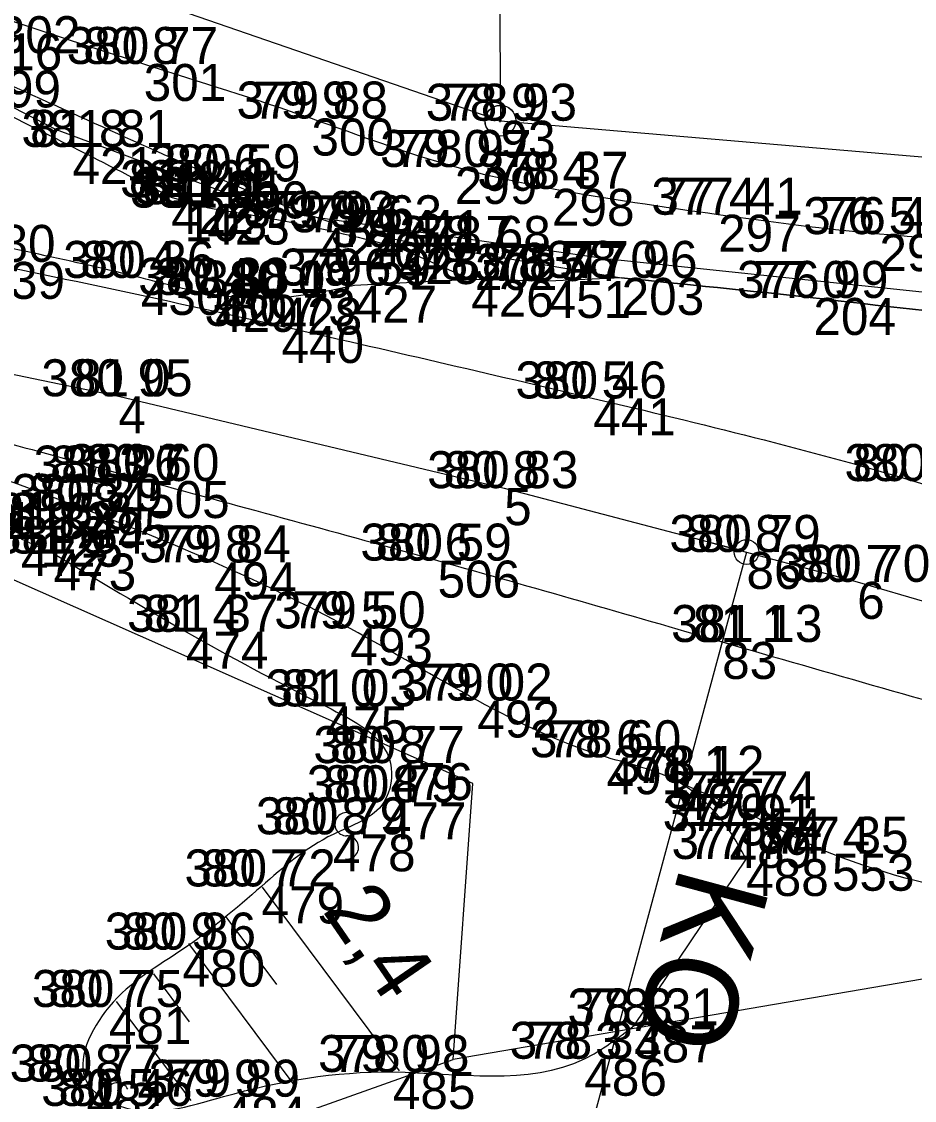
# Model space of a CAD drawing. Extents: x -514509 to -512782, y -1144610 to -1143439.
# Drawn here: x -513064.89 to -513035.93, y -1143617.66 to -1143582.66 of the extents above; entities that cross this region are included whole.
import ezdxf

# ---------------------------------------------------------------- set-up
doc = ezdxf.new("R2010")
doc.units = 0
for name, color, linetype in [('Vrstva 1', 7, 'Continuous'), ('Vrstva 10', 7, 'Continuous'), ('Vrstva 11', 7, 'Continuous'), ('Vrstva 12', 7, 'Continuous'), ('Vrstva 18', 7, 'Continuous'), ('Vrstva 38', 7, 'Continuous'), ('Vrstva 39', 7, 'Continuous'), ('Vrstva 48', 7, 'Continuous'), ('Vrstva 57', 7, 'Continuous'), ('Vrstva 58', 7, 'Continuous'), ('Vrstva 59', 7, 'Continuous'), ('Vrstva 6', 7, 'Continuous'), ('Vrstva 60', 7, 'Continuous'), ('Vrstva 8', 7, 'Continuous')]:
    doc.layers.add(name, color=color, linetype=linetype)

msp = doc.modelspace()

# ---------------------------------------------------------------- linework, layer by layer
at = {"layer": 'Vrstva 1'}
msp.add_lwpolyline([(-513220.491, -1143575.228), (-513193.623, -1143570.982), (-513176.915, -1143569.129), (-513155.694, -1143568.05), (-513138.074, -1143568.989), (-513122.982, -1143570.739), (-513098.68, -1143574.346), (-513082.799, -1143577.731), (-513077.892, -1143579.384), (-513072.257, -1143581.789), (-513063.773, -1143586.163), (-513056.631, -1143588.823), (-513045.948, -1143590.353), (-513035.79, -1143591.42), (-513027.577, -1143592.226), (-513018.616, -1143594.003), (-513003.093, -1143598.799), (-512994.741, -1143602.979), (-512987.23, -1143608.317)], dxfattribs=at)
at = {"layer": 'Vrstva 10'}
for p, q in [((-513049.412, -1143585.881), (-513049.312, -1143585.881)), ((-513049.412, -1143585.881), (-513049.312, -1143585.881)), ((-513049.412, -1143585.881), (-513049.312, -1143585.881)), ((-513049.412, -1143585.881), (-513049.312, -1143585.881)), ((-513049.371, -1143585.929), (-513049.349, -1143585.831)), ((-513049.371, -1143585.929), (-513049.349, -1143585.831)), ((-513049.371, -1143585.929), (-513049.349, -1143585.831))]:
    msp.add_line(p, q, dxfattribs=at)
for points in [[(-513082.58, -1143574.42), (-513049.36, -1143585.88), (-513032.15, -1143587.352), (-513013.645, -1143592.585), (-512996.08, -1143600.301), (-512976.442, -1143595.705), (-512976.456, -1143612.872), (-512962.931, -1143616.56), (-512954.194, -1143606.538), (-512930.452, -1143592.642), (-512928.362, -1143585.895), (-512925.699, -1143603.347)], [(-513082.58, -1143574.42), (-513049.36, -1143585.88), (-513032.15, -1143587.352), (-513013.645, -1143592.585), (-512996.08, -1143600.301), (-512976.442, -1143595.705), (-512976.456, -1143612.872), (-512962.931, -1143616.56), (-512954.194, -1143606.538), (-512930.452, -1143592.642), (-512928.362, -1143585.895), (-512925.699, -1143603.347)], [(-513060.043, -1143588.357), (-513058.868, -1143588.697)], [(-513052.691, -1143589.985), (-513050.308, -1143591.036), (-513054.09, -1143591.229)], [(-513050.191, -1143590.168), (-513045.435, -1143590.979)], [(-513050.191, -1143590.168), (-513045.435, -1143590.979)], [(-513045.435, -1143590.979), (-513047.8, -1143591.081), (-513050.308, -1143591.036)], [(-513064.908, -1143599.447), (-513063.854, -1143599.92)], [(-512782.341, -1143656.666), (-512796.89, -1143661.893), (-512815.309, -1143658.506), (-512846.358, -1143662.813), (-512847.692, -1143673.887), (-512850.552, -1143675.414), (-512874.542, -1143673.507), (-512907.663, -1143668.822), (-512937.442, -1143663.927), (-512942.033, -1143670.511), (-512944.784, -1143662.787), (-512958.978, -1143654.892), (-512977.284, -1143642.016), (-512997.25, -1143628.575), (-513034.474, -1143613.524), (-513050.89, -1143616.331), (-513050.251, -1143607.386), (-513065.331, -1143600.696), (-513084.436, -1143602.206), (-513086.215, -1143618.123), (-513093.877, -1143618.167), (-513107.772, -1143623.787)], [(-512782.341, -1143656.666), (-512796.89, -1143661.893), (-512815.309, -1143658.506), (-512846.358, -1143662.813), (-512847.692, -1143673.887), (-512850.552, -1143675.414), (-512874.542, -1143673.507), (-512907.663, -1143668.822), (-512937.442, -1143663.927), (-512942.033, -1143670.511), (-512944.784, -1143662.787), (-512958.978, -1143654.892), (-512977.284, -1143642.016), (-512997.25, -1143628.575), (-513034.474, -1143613.524), (-513050.89, -1143616.331), (-513050.251, -1143607.386), (-513065.331, -1143600.696), (-513084.436, -1143602.206), (-513086.215, -1143618.123), (-513093.877, -1143618.167), (-513107.772, -1143623.787)], [(-513041.608, -1143608.193), (-513043.544, -1143607.361)], [(-513045.021, -1143615.229), (-513041.387, -1143609.834)], [(-513057.086, -1143610.749), (-513052.65, -1143616.702)], [(-513058.27, -1143611.707), (-513056.621, -1143613.897)], [(-513059.477, -1143612.573), (-513056.026, -1143617.204)], [(-513060.615, -1143613.559), (-513059.458, -1143615.112)], [(-513061.818, -1143614.456), (-513059.403, -1143617.66)]]:
    msp.add_lwpolyline(points, dxfattribs=at)
for centre in [(-513049.362, -1143585.881), (-513049.362, -1143585.881), (-513049.362, -1143585.881), (-513049.362, -1143585.881), (-513049.36, -1143585.88), (-513049.36, -1143585.88), (-513049.36, -1143585.88)]:
    msp.add_circle(centre, 0.499, dxfattribs=at)
for points in [[(-512953.995, -1143613.026), (-512957.258, -1143613.803), (-512961.396, -1143614.272), (-512966.482, -1143614.31), (-512970.759, -1143614.088), (-512973.268, -1143613.625), (-512976.312, -1143612.767), (-512979.387, -1143610.931), (-512983.271, -1143608.165), (-512988.084, -1143604.174), (-512993.595, -1143600.71), (-512999.183, -1143597.931), (-513003.859, -1143595.565), (-513008.344, -1143594.112), (-513012.116, -1143593.309), (-513017.24, -1143592.33), (-513022.405, -1143591.458), (-513027.962, -1143590.755), (-513032.282, -1143589.984), (-513037.071, -1143589.561), (-513042.298, -1143588.932), (-513047.694, -1143588.089), (-513050.837, -1143587.38), (-513055.493, -1143585.813), (-513060.929, -1143584.042), (-513065.663, -1143582.489), (-513071.062, -1143580.47), (-513076.142, -1143578.183), (-513080.606, -1143576.177), (-513085.081, -1143574.916), (-513090.677, -1143573.538)], [(-512953.995, -1143613.026), (-512957.258, -1143613.803), (-512961.396, -1143614.272), (-512966.482, -1143614.31), (-512970.759, -1143614.088), (-512973.268, -1143613.625), (-512976.312, -1143612.767), (-512979.387, -1143610.931), (-512983.271, -1143608.165), (-512988.084, -1143604.174), (-512993.595, -1143600.71), (-512999.183, -1143597.931), (-513003.859, -1143595.565), (-513008.344, -1143594.112), (-513012.116, -1143593.309), (-513017.24, -1143592.33), (-513022.405, -1143591.458), (-513027.962, -1143590.755), (-513032.282, -1143589.984), (-513037.071, -1143589.561), (-513042.298, -1143588.932), (-513047.694, -1143588.089), (-513050.837, -1143587.38), (-513055.493, -1143585.813), (-513060.929, -1143584.042), (-513065.663, -1143582.489), (-513071.062, -1143580.47), (-513076.142, -1143578.183), (-513080.606, -1143576.177), (-513085.081, -1143574.916), (-513090.677, -1143573.538)], [(-513075.063, -1143581.2), (-513072.454, -1143581.842), (-513066.293, -1143584.252), (-513058.25, -1143587.854), (-513053.706, -1143589.505), (-513050.191, -1143590.168)], [(-513075.063, -1143581.2), (-513072.454, -1143581.842), (-513066.293, -1143584.252), (-513058.25, -1143587.854), (-513053.706, -1143589.505), (-513050.191, -1143590.168)], [(-513075.344, -1143581.563), (-513068.994, -1143583.976), (-513063.238, -1143586.73), (-513060.043, -1143588.357)], [(-513054.09, -1143591.229), (-513056.524, -1143591.625), (-513058.608, -1143591.528), (-513061.016, -1143590.979), (-513067.66, -1143589.521), (-513078.163, -1143587.246), (-513090.745, -1143584.896)], [(-513094.522, -1143585.424), (-513085.972, -1143586.813), (-513077.096, -1143588.391), (-513066.158, -1143590.465), (-513056.46, -1143592.544), (-513046.346, -1143594.887), (-513035.955, -1143597.575), (-513025.704, -1143600.949), (-513014.943, -1143604.21), (-513004.729, -1143607.491)], [(-513058.868, -1143588.697), (-513055.265, -1143589.361), (-513052.691, -1143589.985)], [(-513045.435, -1143590.979), (-513039.213, -1143591.629), (-513032.779, -1143592.299), (-513026.133, -1143592.81), (-513019.57, -1143594.143), (-513014.993, -1143595.23), (-513009.333, -1143597.099), (-513004.427, -1143598.943), (-513000.195, -1143600.648), (-512995.465, -1143603.755), (-512990.482, -1143606.95), (-512986.481, -1143609.695), (-512982.688, -1143612.309), (-512979.1, -1143614.259), (-512976.081, -1143615.456), (-512973.855, -1143616.04), (-512971.299, -1143616.182), (-512967.877, -1143616.452), (-512963.669, -1143616.372), (-512959.668, -1143616.236), (-512956.333, -1143615.735)], [(-513045.435, -1143590.979), (-513039.213, -1143591.629), (-513032.779, -1143592.299), (-513026.133, -1143592.81), (-513019.57, -1143594.143), (-513014.993, -1143595.23), (-513009.333, -1143597.099), (-513004.427, -1143598.943), (-513000.195, -1143600.648), (-512995.465, -1143603.755), (-512990.482, -1143606.95), (-512986.481, -1143609.695), (-512982.688, -1143612.309), (-512979.1, -1143614.259), (-512976.081, -1143615.456), (-512973.855, -1143616.04), (-512971.299, -1143616.182), (-512967.877, -1143616.452), (-512963.669, -1143616.372), (-512959.668, -1143616.236), (-512956.333, -1143615.735)], [(-512979.1, -1143614.259), (-512982.688, -1143612.309), (-512986.481, -1143609.695), (-512990.482, -1143606.95), (-512995.465, -1143603.755), (-513000.195, -1143600.648), (-513004.427, -1143598.943), (-513009.333, -1143597.099), (-513014.993, -1143595.23), (-513019.57, -1143594.143), (-513026.133, -1143592.81), (-513032.779, -1143592.299), (-513039.213, -1143591.629), (-513045.435, -1143590.979)], [(-513091.48, -1143591.211), (-513084.48, -1143592.318), (-513076.865, -1143593.708), (-513068.286, -1143595.582), (-513060.823, -1143597.567), (-513051.402, -1143600.148), (-513042.167, -1143602.79), (-513031.788, -1143605.729), (-513027.378, -1143606.917)], [(-513041.387, -1143609.834), (-513041.931, -1143608.916), (-513043.544, -1143607.361), (-513045.917, -1143606.531), (-513050.108, -1143604.688), (-513054.233, -1143602.354), (-513058.64, -1143600.206), (-513062.712, -1143598.536), (-513069.216, -1143596.302), (-513075.014, -1143594.932), (-513083.059, -1143593.63), (-513093.377, -1143592.318)], [(-513063.854, -1143599.92), (-513059.557, -1143602.457), (-513055.027, -1143604.877), (-513052.926, -1143606.719), (-513053.141, -1143607.989), (-513054.788, -1143609.032), (-513057.112, -1143610.72), (-513059.667, -1143612.765), (-513062.056, -1143614.633), (-513062.783, -1143617.052), (-513061.726, -1143617.841), (-513058.344, -1143617.537), (-513052.854, -1143616.739), (-513046.637, -1143616.314), (-513045.021, -1143615.229)], [(-512993.539, -1143625.829), (-513001.654, -1143622.116), (-513007.851, -1143619.347), (-513015.061, -1143617.108), (-513021.554, -1143615.482), (-513027.253, -1143613.027), (-513033.075, -1143611.223), (-513038.613, -1143609.661), (-513041.608, -1143608.193)]]:
    msp.add_spline(points, degree=3, dxfattribs=at)
at = {"layer": 'Vrstva 12'}
for p, q in [((-513062.479, -1143597.131), (-513062.696, -1143598.108)), ((-513063.076, -1143597.511), (-513062.099, -1143597.728)), ((-513042.036, -1143602.307), (-513042.297, -1143603.272)), ((-513042.649, -1143602.659), (-513041.684, -1143602.92))]:
    msp.add_line(p, q, dxfattribs=at)
at = {"layer": 'Vrstva 18'}
for centre, radius, start, end in [((-513054.353, -1143608.702), 0.376, 84.3625, 270.6736), ((-513054.34, -1143609.455), 0.377, 263.6864, 91.3496), ((-513061.786, -1143617.464), 0.376, 25.7026, 212.0138)]:
    msp.add_arc(centre, radius, start, end, dxfattribs=at)
at = {"layer": 'Vrstva 38'}
msp.add_circle((-513041.38, -1143599.872), 0.4, dxfattribs=at)
at = {"layer": 'Vrstva 39'}
msp.add_lwpolyline([(-513041.38, -1143599.872), (-513042.167, -1143602.79), (-513051.797, -1143638.491)], dxfattribs=at)
at = {"layer": 'Vrstva 48'}
msp.add_line((-513049.412, -1143585.881), (-513049.312, -1143585.881), dxfattribs=at)
msp.add_circle((-513049.362, -1143585.881), 0.499, dxfattribs=at)
at = {"layer": 'Vrstva 6'}
for points in [[(-513098.478, -1143588.28), (-513086.339, -1143590.12), (-513074.133, -1143592.245), (-513061.751, -1143594.815), (-513049.24, -1143597.798), (-513041.788, -1143599.762)], [(-513042.471, -1143599.582), (-513037.794, -1143600.839), (-513025.951, -1143604.295), (-513021.487, -1143605.723), (-513009.806, -1143609.501), (-513001.948, -1143612.085)]]:
    msp.add_lwpolyline(points, dxfattribs=at)
at = {"layer": 'Vrstva 60'}
for p, q in [((-513060.93, -1143584.04), (-513060.93, -1143584.04)), ((-513055.49, -1143585.81), (-513055.49, -1143585.81)), ((-513049.36, -1143585.88), (-513049.36, -1143585.88)), ((-513063.24, -1143586.73), (-513063.24, -1143586.73)), ((-513050.84, -1143587.38), (-513050.84, -1143587.38)), ((-513058.25, -1143587.85), (-513058.25, -1143587.85)), ((-513047.69, -1143588.09), (-513047.69, -1143588.09)), ((-513060.04, -1143588.36), (-513060.04, -1143588.36)), ((-513059.6, -1143588.59), (-513059.6, -1143588.59)), ((-513058.87, -1143588.7), (-513058.87, -1143588.7)), ((-513042.3, -1143588.93), (-513042.3, -1143588.93)), ((-513055.26, -1143589.36), (-513055.26, -1143589.36)), ((-513053.71, -1143589.5), (-513053.71, -1143589.5)), ((-513037.07, -1143589.56), (-513037.07, -1143589.56)), ((-513052.69, -1143589.98), (-513052.69, -1143589.98)), ((-513050.19, -1143590.17), (-513050.19, -1143590.17)), ((-513061.02, -1143590.98), (-513061.02, -1143590.98)), ((-513045.43, -1143590.98), (-513045.43, -1143590.98)), ((-513054.09, -1143591.23), (-513054.09, -1143591.23)), ((-513050.31, -1143591.04), (-513050.31, -1143591.04)), ((-513047.8, -1143591.08), (-513047.8, -1143591.08)), ((-513058.61, -1143591.53), (-513058.61, -1143591.53)), ((-513056.52, -1143591.62), (-513056.52, -1143591.62)), ((-513039.21, -1143591.63), (-513039.21, -1143591.63)), ((-513056.46, -1143592.54), (-513056.46, -1143592.54)), ((-513061.75, -1143594.82), (-513061.75, -1143594.82)), ((-513046.35, -1143594.89), (-513046.35, -1143594.89)), ((-513062.59, -1143597.62), (-513062.59, -1143597.62)), ((-513060.82, -1143597.57), (-513060.82, -1143597.57)), ((-513035.96, -1143597.57), (-513035.96, -1143597.57)), ((-513049.24, -1143597.8), (-513049.24, -1143597.8)), ((-513062.71, -1143598.54), (-513062.71, -1143598.54)), ((-513064.28, -1143599.15), (-513064.28, -1143599.15)), ((-513063.85, -1143599.92), (-513063.85, -1143599.92)), ((-513041.38, -1143599.87), (-513041.38, -1143599.87)), ((-513058.64, -1143600.21), (-513058.64, -1143600.21)), ((-513051.4, -1143600.15), (-513051.4, -1143600.15)), ((-513037.79, -1143600.84), (-513037.79, -1143600.84)), ((-513059.56, -1143602.46), (-513059.56, -1143602.46)), ((-513054.23, -1143602.35), (-513054.23, -1143602.35)), ((-513042.17, -1143602.79), (-513042.17, -1143602.79)), ((-513055.03, -1143604.88), (-513055.03, -1143604.88)), ((-513050.11, -1143604.69), (-513050.11, -1143604.69)), ((-513052.93, -1143606.72), (-513052.93, -1143606.72)), ((-513045.92, -1143606.53), (-513045.92, -1143606.53)), ((-513043.54, -1143607.36), (-513043.54, -1143607.36)), ((-513053.14, -1143607.99), (-513053.14, -1143607.99)), ((-513041.61, -1143608.19), (-513041.61, -1143608.19)), ((-513054.79, -1143609.03), (-513054.79, -1143609.03)), ((-513041.93, -1143608.92), (-513041.93, -1143608.92)), ((-513041.39, -1143609.83), (-513041.39, -1143609.83)), ((-513038.61, -1143609.66), (-513038.61, -1143609.66)), ((-513057.11, -1143610.72), (-513057.11, -1143610.72)), ((-513059.67, -1143612.77), (-513059.67, -1143612.77)), ((-513062.06, -1143614.63), (-513062.06, -1143614.63)), ((-513045.02, -1143615.23), (-513045.02, -1143615.23)), ((-513046.64, -1143616.31), (-513046.64, -1143616.31)), ((-513052.85, -1143616.74), (-513052.85, -1143616.74)), ((-513062.78, -1143617.05), (-513062.78, -1143617.05)), ((-513058.34, -1143617.54), (-513058.34, -1143617.54))]:
    msp.add_line(p, q, dxfattribs=at)
at = {"layer": 'Vrstva 8'}
for points in [[(-513066.715, -1143494.873), (-513051.738, -1143489.896), (-513050.167, -1143533.331), (-513049.523, -1143563.665), (-513049.36, -1143585.88)], [(-513086.215, -1143618.123), (-513061.648, -1143620.161), (-513050.89, -1143616.331)]]:
    msp.add_lwpolyline(points, dxfattribs=at)

# ---------------------------------------------------------------- texts
at = {"layer": 'Vrstva 11'}
msp.add_text('2,4', height=2, rotation=304.5175, dxfattribs=at).set_placement((-513055.157, -1143611.503))
at = {"layer": 'Vrstva 39'}
msp.add_text('KO', height=3, rotation=254.9047, dxfattribs=at).set_placement((-513043.508, -1143609.984))
at = {"layer": 'Vrstva 57'}
for s, p in [('80 8 ', (-513062.89, -1143584.04)), ('79 9 ', (-513057.386, -1143585.81)), ('78 9 ', (-513051.248, -1143585.88)), ('81 8 ', (-513064.613, -1143586.73)), ('79 0 ', (-513052.794, -1143587.38)), ('80 6 ', (-513060.252, -1143587.85)), ('81 2 ', (-513061.413, -1143588.36)), ('78 4 ', (-513049.573, -1143588.09)), ('81 4 ', (-513060.973, -1143588.59)), ('81 0 ', (-513060.308, -1143588.7)), ('77 4 ', (-513044.183, -1143588.93)), ('79 9 ', (-513057.156, -1143589.36)), ('79 6 ', (-513055.641, -1143589.5)), ('76 5 ', (-513039.002, -1143589.56)), ('79 4 ', (-513054.58, -1143589.98)), ('78 7 ', (-513052.073, -1143590.17)), ('80 4 ', (-513062.98, -1143590.98)), ('78 8 ', (-513052.193, -1143591.04)), ('78 5 ', (-513049.683, -1143591.08)), ('78 0 ', (-513047.378, -1143590.98)), ('80 4 ', (-513060.57, -1143591.53)), ('79 6 ', (-513056.021, -1143591.23)), ('80 1 ', (-513058.056, -1143591.62)), ('77 0 ', (-513041.158, -1143591.63)), ('80 7 ', (-513058.42, -1143592.54)), ('81 0 ', (-513063.188, -1143594.82)), ('80 5 ', (-513048.31, -1143594.89)), ('81 3 ', (-513063.963, -1143597.62)), ('80 6 ', (-513062.822, -1143597.57)), ('80 8 ', (-513051.2, -1143597.8)), ('80 2 ', (-513037.92, -1143597.57)), ('80 3 ', (-513064.67, -1143598.54)), ('81 6 ', (-513065.694, -1143599.15)), ('81 8 ', (-513066.283, -1143599.45)), ('81 6 ', (-513065.264, -1143599.92)), ('80 8 ', (-513043.34, -1143599.87)), ('79 8 ', (-513060.53, -1143600.21)), ('80 6 ', (-513053.402, -1143600.15)), ('80 7 ', (-513039.75, -1143600.84)), ('79 5 ', (-513056.12, -1143602.35)), ('81 4 ', (-513060.933, -1143602.46)), ('81 1 ', (-513043.118, -1143602.79)), ('79 0 ', (-513052.064, -1143604.69)), ('81 0 ', (-513056.468, -1143604.88)), ('78 6 ', (-513047.844, -1143606.53)), ('80 8 ', (-513054.89, -1143606.72)), ('78 1 ', (-513044.998, -1143607.36)), ('80 8 ', (-513055.1, -1143607.99)), ('77 7 ', (-513043.493, -1143608.19)), ('80 8 ', (-513056.75, -1143609.03)), ('77 9 ', (-513043.818, -1143608.92)), ('77 4 ', (-513040.493, -1143609.66)), ('77 7 ', (-513043.273, -1143609.83)), ('80 7 ', (-513059.07, -1143610.72)), ('80 9 ', (-513061.636, -1143612.77)), ('80 7 ', (-513064.02, -1143614.63)), ('78 3 ', (-513046.903, -1143615.23)), ('78 3 ', (-513048.523, -1143616.31)), ('79 0 ', (-513054.804, -1143616.74)), ('80 8 ', (-513064.74, -1143617.05)), ('79 9 ', (-513060.236, -1143617.54)), ('80 5 ', (-513063.69, -1143617.84))]:
    msp.add_text(s, height=1.2, dxfattribs=at).set_placement(p)
at = {"layer": 'Vrstva 58'}
for s, p in [('380 77', (-513063.428, -1143584.04)), ('382 16', (-513068.48, -1143584.25)), ('379 88', (-513057.918, -1143585.81)), ('378 93', (-513051.784, -1143585.88)), ('381 81', (-513064.896, -1143586.73)), ('378 97', (-513053.264, -1143587.38)), ('380 59', (-513060.752, -1143587.85)), ('381 21', (-513061.696, -1143588.36)), ('378 37', (-513050.111, -1143588.09)), ('380 95', (-513061.372, -1143588.7)), ('381 41', (-513061.256, -1143588.59)), ('377 41', (-513044.466, -1143588.93)), ('379 93', (-513057.692, -1143589.36)), ('379 63', (-513056.162, -1143589.5)), ('376 45', (-513039.54, -1143589.56)), ('379 41', (-513054.863, -1143589.98)), ('380 80', (-513068.698, -1143590.46)), ('378 68', (-513052.636, -1143590.17)), ('380 36', (-513063.544, -1143590.98)), ('378 76', (-513052.756, -1143591.04)), ('378 47', (-513050.221, -1143591.08)), ('377 96', (-513047.879, -1143590.98)), ('380 38', (-513061.108, -1143591.53)), ('379 59', (-513056.522, -1143591.23)), ('380 09', (-513059.061, -1143591.62)), ('376 99', (-513041.688, -1143591.63)), ('380 73', (-513058.958, -1143592.54)), ('380 95', (-513064.252, -1143594.82)), ('380 46', (-513048.874, -1143594.89)), ('381 27', (-513064.501, -1143597.62)), ('380 60', (-513063.382, -1143597.57)), ('380 83', (-513051.738, -1143597.8)), ('380 17', (-513038.204, -1143597.57)), ('380 29', (-513065.212, -1143598.54)), ('381 58', (-513066.191, -1143599.15)), ('381 83', (-513066.821, -1143599.45)), ('381 64', (-513065.786, -1143599.92)), ('380 79', (-513043.882, -1143599.87)), ('379 84', (-513061.068, -1143600.21)), ('380 59', (-513053.902, -1143600.15)), ('380 70', (-513040.328, -1143600.84)), ('379 50', (-513056.696, -1143602.35)), ('381 37', (-513061.471, -1143602.46)), ('381 13', (-513043.826, -1143602.79)), ('379 02', (-513052.576, -1143604.69)), ('381 03', (-513056.98, -1143604.88)), ('378 60', (-513048.404, -1143606.53)), ('380 77', (-513055.428, -1143606.72)), ('378 12', (-513045.706, -1143607.36)), ('380 79', (-513055.642, -1143607.99)), ('377 74', (-513044.031, -1143608.19)), ('380 79', (-513057.292, -1143609.03)), ('377 91', (-513044.1, -1143608.92)), ('377 35', (-513041.031, -1143609.66)), ('377 74', (-513043.811, -1143609.83)), ('380 72', (-513059.608, -1143610.72)), ('380 86', (-513062.194, -1143612.77)), ('380 75', (-513064.558, -1143614.63)), ('378 31', (-513047.186, -1143615.23)), ('378 33', (-513049.061, -1143616.31)), ('378 98', (-513055.274, -1143616.74)), ('380 77', (-513065.278, -1143617.05)), ('379 89', (-513060.772, -1143617.54)), ('380 46', (-513064.254, -1143617.84))]:
    msp.add_text(s, height=1.2, dxfattribs=at).set_placement(p)
at = {"layer": 'Vrstva 59'}
for s, p in [('302', (-513065.66, -1143583.69)), ('301', (-513060.93, -1143585.24)), ('199', (-513066.29, -1143585.45)), ('300', (-513055.49, -1143587.01)), ('93', (-513049.36, -1143587.08)), ('421', (-513063.24, -1143587.93)), ('299', (-513050.84, -1143588.58)), ('200', (-513058.25, -1143589.05)), ('298', (-513047.69, -1143589.29)), ('422', (-513060.04, -1143589.56)), ('103', (-513059.6, -1143589.79)), ('423', (-513058.87, -1143589.9)), ('297', (-513042.3, -1143590.13)), ('424', (-513055.26, -1143590.56)), ('201', (-513053.71, -1143590.7)), ('296', (-513037.07, -1143590.76)), ('425', (-513052.69, -1143591.18)), ('202', (-513050.19, -1143591.37)), ('439', (-513066.16, -1143591.66)), ('430', (-513061.02, -1143592.18)), ('426', (-513050.31, -1143592.24)), ('203', (-513045.43, -1143592.18)), ('427', (-513054.09, -1143592.43)), ('451', (-513047.8, -1143592.28)), ('429', (-513058.61, -1143592.73)), ('428', (-513056.52, -1143592.82)), ('204', (-513039.21, -1143592.83)), ('440', (-513056.46, -1143593.74)), ('4', (-513061.75, -1143596.02)), ('441', (-513046.35, -1143596.09)), ('84', (-513062.59, -1143598.82)), ('505', (-513060.82, -1143598.77)), ('5', (-513049.24, -1143599)), ('495', (-513062.71, -1143599.74)), ('125', (-513064.28, -1143600.35)), ('472', (-513064.91, -1143600.65)), ('473', (-513063.85, -1143601.12)), ('86', (-513041.38, -1143601.07)), ('494', (-513058.64, -1143601.41)), ('506', (-513051.4, -1143601.35)), ('6', (-513037.79, -1143602.04)), ('474', (-513059.56, -1143603.66)), ('493', (-513054.23, -1143603.55)), ('83', (-513042.17, -1143603.99)), ('492', (-513050.11, -1143605.89)), ('475', (-513055.03, -1143606.08)), ('476', (-513052.93, -1143607.92)), ('491', (-513045.92, -1143607.73)), ('490', (-513043.54, -1143608.56)), ('477', (-513053.14, -1143609.19)), ('554', (-513041.61, -1143609.39)), ('478', (-513054.79, -1143610.23)), ('489', (-513041.93, -1143610.12)), ('488', (-513041.39, -1143611.03)), ('553', (-513038.61, -1143610.86)), ('479', (-513057.11, -1143611.92)), ('480', (-513059.67, -1143613.97)), ('481', (-513062.06, -1143615.83)), ('487', (-513045.02, -1143616.43)), ('486', (-513046.64, -1143617.51)), ('485', (-513052.85, -1143617.94)), ('482', (-513062.78, -1143618.25)), ('484', (-513058.34, -1143618.74))]:
    msp.add_text(s, height=1.2, dxfattribs=at).set_placement(p)

doc.saveas('drawing.dxf')
